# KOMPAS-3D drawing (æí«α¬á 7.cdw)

Views: Вид 1, Вид 2, Вид 3
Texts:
  Редуктор коническо-цилиндрический  Сборочный чертеж
  Беляев Андрей Константинович
  Noncommercial version
  уровень масла
  Мощность на быстро-
  ходном валу, кВт
  Частота вращения быст-
  роходного вала, об/мин
  Номинальный крутящий
  момент на выходном валу, Н м
  Symbol type A
  Общее передаточное отношение
  Ступень
  Передаточное число
  Число
  зубьев
  Модуль нормальный, мм
  Окружная скорость
  в зацеплении, м/с
  Степень точности передачи
  Шестерня
  Колесо
  Быстроходная
  Тихоходная
  Техническая характеристика редуктора:
  Регулировка конического зацепления производится
  металлическими прокладками позиция 47.
  Полости между подшипниками конического вала-шестерни
  заполнить солидолом УС-2 ГОСТ 1033-73.
  При сборке поверхности разъема крышки и картера редуктора
  покрыть герметиком УЗОМ ГОСТ 13489-79.
  После сборки залить в редуктор масло ВНИИ НП-403 ГОСТ
  16728-78 на 15-20 мм выше верхней риски маслоуказателя. Объем
  заливаемого масла  10 л.
  Редуктор подлежит обкатке в течение 1,5 часов с
  периодическим реверсом передачи.
  Болты для крепления всех крышек на виде сверху условно
  показаны в плоскости разъема картера и крышки корпуса..
  При необходимости возможно цилиндрическое исполнение
  концов валов.
  Шпонка
  ГОСТ
  Рым-болт М20.19 ГОСТ 4751-73
  Болт
  Рым-болт
  Редуктор
  коническо-цилиндрический
  Сборочный чертеж
Dimensions and other numbers on the sheet: 70; 65; 110; 200; 130; 82; 28; 50; 60; 705; 250; 425; 1005; 635; 44; 165; 95; 360; 305; 325; 150; 75; 505; 255; 1; 2; 3; 4; 5; 6; 7; 8; 9; 10; 11; 12; 13; 14; 15; 16; 17; 18; 19; 22; 23; 24; 25; 26; 27; 29; 30; 31; 32; 33; 34; 35; 36; 37; 38; 39; 40; 41; 42; 43; 45; 46; 47; 21,78; 735; 4150; 15,489; 3,53; 2,82; 8-В; 4,388; 79; 0,985; 9-В; 48,5; 117; 78; -6g; 73; 1:2,5; 412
